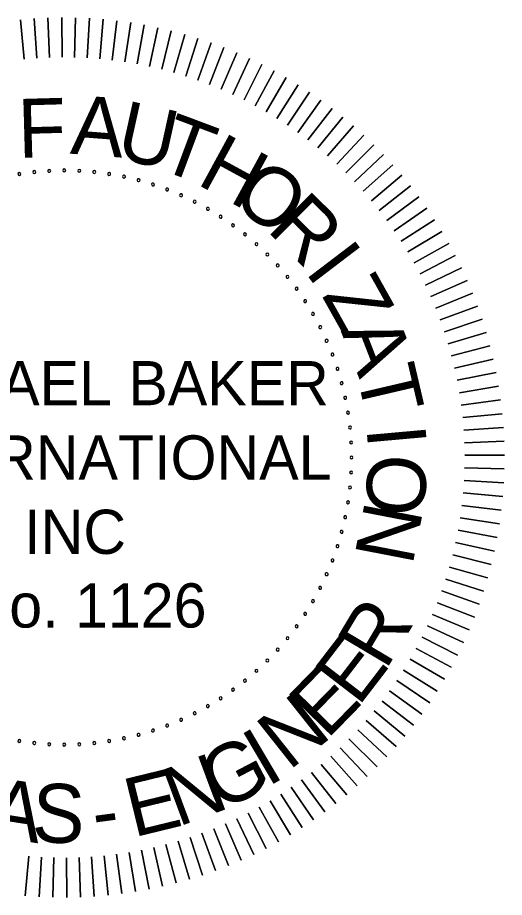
# Model space of a CAD drawing. Extents: x -35254 to 17396, y -8913 to 11592.
# Drawn here: x 6524 to 7900, y -5972 to -3484 of the extents above; entities that cross this region are included whole.
import ezdxf

# ---------------------------------------------------------------- set-up
doc = ezdxf.new("R2010")
doc.units = 0
doc.layers.add('G-ANNO-TEXT', color=7, linetype='Continuous')

msp = doc.modelspace()

# ---------------------------------------------------------------- linework, layer by layer
at = {"layer": 'G-ANNO-TEXT'}
for points in [[(6649.7, -3595.9), (6649.1, -3483.7)], [(6649.1, -3483.7), (6649.7, -3595.9)], [(6685.3, -3596.3), (6688.2, -3484.1)], [(6688.2, -3484.1), (6685.3, -3596.3)], [(6543.2, -3601.5), (6532, -3489.9)], [(6532, -3489.9), (6543.2, -3601.5)], [(6578.7, -3598.6), (6571, -3486.6)], [(6571, -3486.6), (6578.7, -3598.6)], [(6614.2, -3596.7), (6610, -3484.5)], [(6610, -3484.5), (6614.2, -3596.7)], [(6720.8, -3597.8), (6727.3, -3485.7)], [(6727.3, -3485.7), (6720.8, -3597.8)], [(6756.3, -3600.4), (6766.3, -3488.6)], [(6766.3, -3488.6), (6756.3, -3600.4)], [(6791.7, -3604.1), (6805.1, -3492.6)], [(6805.1, -3492.6), (6791.7, -3604.1)], [(6826.9, -3608.9), (6843.9, -3497.9)], [(6843.9, -3497.9), (6826.9, -3608.9)], [(6862, -3614.8), (6882.4, -3504.4)], [(6882.4, -3504.4), (6862, -3614.8)], [(6896.9, -3621.8), (6920.7, -3512.2)], [(6920.7, -3512.2), (6896.9, -3621.8)], [(6931.5, -3629.9), (6958.8, -3521.1)], [(6958.8, -3521.1), (6931.5, -3629.9)], [(6965.9, -3639.1), (6996.6, -3531.2)], [(6996.6, -3531.2), (6965.9, -3639.1)], [(6999.9, -3649.4), (7034, -3542.5)], [(7034, -3542.5), (6999.9, -3649.4)], [(7033.6, -3660.7), (7071, -3554.9)], [(7071, -3554.9), (7033.6, -3660.7)], [(7067, -3673.1), (7107.7, -3568.5)], [(7107.7, -3568.5), (7067, -3673.1)], [(7099.9, -3686.5), (7143.9, -3583.3)], [(7143.9, -3583.3), (7099.9, -3686.5)], [(7132.4, -3701), (7179.6, -3599.2)], [(7179.6, -3599.2), (7132.4, -3701)], [(7164.4, -3716.5), (7214.8, -3616.2)], [(7214.8, -3616.2), (7164.4, -3716.5)], [(7195.9, -3732.9), (7249.5, -3634.3)], [(7249.5, -3634.3), (7195.9, -3732.9)], [(7226.9, -3750.4), (7283.5, -3653.5)], [(7283.5, -3653.5), (7226.9, -3750.4)], [(7257.4, -3768.8), (7317, -3673.7)], [(7317, -3673.7), (7257.4, -3768.8)], [(7287.2, -3788.2), (7349.8, -3695)], [(7349.8, -3695), (7287.2, -3788.2)], [(7316.4, -3808.4), (7381.9, -3717.3)], [(7381.9, -3717.3), (7316.4, -3808.4)], [(7345, -3829.6), (7413.3, -3740.6)], [(7413.3, -3740.6), (7345, -3829.6)], [(7372.9, -3851.7), (7443.9, -3764.9)], [(7443.9, -3764.9), (7372.9, -3851.7)], [(7400, -3874.7), (7473.8, -3790.1)], [(7473.8, -3790.1), (7400, -3874.7)], [(7502.8, -3816.2), (7426.5, -3898.5)], [(7426.5, -3898.5), (7502.8, -3816.2)], [(7531.1, -3843.3), (7452.2, -3923.1)], [(7452.2, -3923.1), (7531.1, -3843.3)], [(7558.4, -3871.2), (7477, -3948.5)], [(7477, -3948.5), (7558.4, -3871.2)], [(7584.9, -3900), (7501.1, -3974.6)], [(7501.1, -3974.6), (7584.9, -3900)], [(7610.4, -3929.5), (7524.4, -4001.6)], [(7524.4, -4001.6), (7610.4, -3929.5)], [(7635.1, -3959.9), (7546.8, -4029.2)], [(7546.8, -4029.2), (7635.1, -3959.9)], [(7658.7, -3991), (7568.3, -4057.5)], [(7568.3, -4057.5), (7658.7, -3991)], [(7681.4, -4022.9), (7588.9, -4086.5)], [(7588.9, -4086.5), (7681.4, -4022.9)], [(7703, -4055.5), (7608.6, -4116.1)], [(7608.6, -4116.1), (7703, -4055.5)], [(7723.6, -4088.7), (7627.3, -4146.3)], [(7627.3, -4146.3), (7723.6, -4088.7)], [(7743.2, -4122.5), (7645.1, -4177.1)], [(7645.1, -4177.1), (7743.2, -4122.5)], [(7761.7, -4157), (7662, -4208.5)], [(7662, -4208.5), (7761.7, -4157)], [(7779.1, -4192), (7677.8, -4240.3)], [(7677.8, -4240.3), (7779.1, -4192)], [(7795.3, -4227.5), (7692.6, -4272.7)], [(7692.6, -4272.7), (7795.3, -4227.5)], [(7810.5, -4263.6), (7706.4, -4305.4)], [(7706.4, -4305.4), (7810.5, -4263.6)], [(7824.5, -4300), (7719.1, -4338.6)], [(7719.1, -4338.6), (7824.5, -4300)], [(7837.4, -4337), (7730.9, -4372.2)], [(7730.9, -4372.2), (7837.4, -4337)], [(7849.1, -4374.3), (7741.5, -4406.2)], [(7741.5, -4406.2), (7849.1, -4374.3)], [(7859.6, -4411.9), (7751.1, -4440.4)], [(7751.1, -4440.4), (7859.6, -4411.9)], [(7869, -4449.9), (7759.6, -4475)], [(7759.6, -4475), (7869, -4449.9)], [(7877.1, -4488.1), (7767, -4509.7)], [(7767, -4509.7), (7877.1, -4488.1)], [(7884, -4526.6), (7773.3, -4544.8)], [(7773.3, -4544.8), (7884, -4526.6)], [(7889.8, -4565.3), (7778.5, -4579.9)], [(7778.5, -4579.9), (7889.8, -4565.3)], [(7894.3, -4604.1), (7782.6, -4615.3)], [(7782.6, -4615.3), (7894.3, -4604.1)], [(7897.5, -4643), (7785.6, -4650.7)], [(7785.6, -4650.7), (7897.5, -4643)], [(7899.6, -4682.1), (7787.5, -4686.2)], [(7787.5, -4686.2), (7899.6, -4682.1)], [(7900.4, -4721.2), (7788.2, -4721.8)], [(7788.2, -4721.8), (7900.4, -4721.2)], [(7900, -4760.3), (7787.9, -4757.4)], [(7787.9, -4757.4), (7900, -4760.3)], [(7898.4, -4799.3), (7786.4, -4792.9)], [(7786.4, -4792.9), (7898.4, -4799.3)], [(7895.6, -4838.3), (7783.8, -4828.4)], [(7783.8, -4828.4), (7895.6, -4838.3)], [(7891.5, -4877.2), (7780.1, -4863.7)], [(7780.1, -4863.7), (7891.5, -4877.2)], [(7886.2, -4915.9), (7775.3, -4899)], [(7775.3, -4899), (7886.2, -4915.9)], [(7879.7, -4954.5), (7769.3, -4934)], [(7769.3, -4934), (7879.7, -4954.5)], [(7872, -4992.8), (7762.3, -4968.9)], [(7762.3, -4968.9), (7872, -4992.8)], [(7863.1, -5030.8), (7754.2, -5003.5)], [(7754.2, -5003.5), (7863.1, -5030.8)], [(7853, -5068.6), (7745, -5037.9)], [(7745, -5037.9), (7853, -5068.6)], [(7841.7, -5106), (7734.8, -5072)], [(7734.8, -5072), (7841.7, -5106)], [(7829.2, -5143.1), (7723.4, -5105.7)], [(7723.4, -5105.7), (7829.2, -5143.1)], [(7815.6, -5179.7), (7711, -5139)], [(7711, -5139), (7815.6, -5179.7)], [(7800.8, -5215.9), (7697.6, -5171.9)], [(7697.6, -5171.9), (7800.8, -5215.9)], [(7785, -5251.7), (7683.2, -5204.4)], [(7683.2, -5204.4), (7785, -5251.7)], [(7768, -5286.9), (7667.7, -5236.5)], [(7667.7, -5236.5), (7768, -5286.9)], [(7749.9, -5321.5), (7651.2, -5268)], [(7651.2, -5268), (7749.9, -5321.5)], [(7730.7, -5355.6), (7633.8, -5299)], [(7633.8, -5299), (7730.7, -5355.6)], [(7710.4, -5389), (7615.4, -5329.4)], [(7615.4, -5329.4), (7710.4, -5389)], [(7689.2, -5421.8), (7596, -5359.2)], [(7596, -5359.2), (7689.2, -5421.8)], [(7666.9, -5453.9), (7575.7, -5388.5)], [(7575.7, -5388.5), (7666.9, -5453.9)], [(7643.6, -5485.3), (7554.5, -5417)], [(7554.5, -5417), (7643.6, -5485.3)], [(7619.3, -5516), (7532.4, -5444.9)], [(7532.4, -5444.9), (7619.3, -5516)], [(7594.1, -5545.8), (7509.5, -5472.1)], [(7509.5, -5472.1), (7594.1, -5545.8)], [(7567.9, -5574.9), (7485.7, -5498.5)], [(7485.7, -5498.5), (7567.9, -5574.9)], [(7540.9, -5603.1), (7461.1, -5524.2)], [(7461.1, -5524.2), (7540.9, -5603.1)], [(7512.9, -5630.5), (7435.7, -5549.1)], [(7435.7, -5549.1), (7512.9, -5630.5)], [(7484.2, -5656.9), (7409.5, -5573.2)], [(7409.5, -5573.2), (7484.2, -5656.9)], [(7454.6, -5682.5), (7382.6, -5596.4)], [(7382.6, -5596.4), (7454.6, -5682.5)], [(7424.2, -5707.1), (7354.9, -5618.8)], [(7354.9, -5618.8), (7424.2, -5707.1)], [(7393.1, -5730.8), (7326.6, -5640.3)], [(7326.6, -5640.3), (7393.1, -5730.8)], [(7361.2, -5753.4), (7297.6, -5660.9)], [(7297.6, -5660.9), (7361.2, -5753.4)], [(7328.7, -5775.1), (7268, -5680.6)], [(7268, -5680.6), (7328.7, -5775.1)], [(7261.6, -5815.2), (7207, -5717.2)], [(7207, -5717.2), (7261.6, -5815.2)], [(7295.5, -5795.7), (7237.8, -5699.4)], [(7237.8, -5699.4), (7295.5, -5795.7)], [(7227.2, -5833.7), (7175.7, -5734)], [(7175.7, -5734), (7227.2, -5833.7)], [(7156.6, -5867.4), (7111.5, -5764.6)], [(7111.5, -5764.6), (7156.6, -5867.4)], [(7192.2, -5851.1), (7143.8, -5749.8)], [(7143.8, -5749.8), (7192.2, -5851.1)], [(7084.1, -5896.6), (7045.5, -5791.2)], [(7045.5, -5791.2), (7084.1, -5896.6)], [(7120.6, -5882.5), (7078.7, -5778.4)], [(7078.7, -5778.4), (7120.6, -5882.5)], [(6972.2, -5931.7), (6943.7, -5823.1)], [(6943.7, -5823.1), (6972.2, -5931.7)], [(7009.9, -5921.1), (6978, -5813.5)], [(6978, -5813.5), (7009.9, -5921.1)], [(7047.2, -5909.4), (7011.9, -5802.9)], [(7011.9, -5802.9), (7047.2, -5909.4)], [(6857.6, -5956.1), (6839.4, -5845.3)], [(6839.4, -5845.3), (6857.6, -5956.1)], [(6896, -5949.1), (6874.4, -5839)], [(6874.4, -5839), (6896, -5949.1)], [(6934.3, -5941), (6909.2, -5831.6)], [(6909.2, -5831.6), (6934.3, -5941)], [(6545.8, -5967.6), (6555.8, -5855.8)], [(6555.8, -5855.8), (6545.8, -5967.6)], [(6584.8, -5970.5), (6591.3, -5858.4)], [(6591.3, -5858.4), (6584.8, -5970.5)], [(6623.9, -5972.1), (6626.8, -5859.9)], [(6626.8, -5859.9), (6623.9, -5972.1)], [(6663, -5972.5), (6662.4, -5860.3)], [(6662.4, -5860.3), (6663, -5972.5)], [(6702.1, -5971.7), (6697.9, -5859.5)], [(6697.9, -5859.5), (6702.1, -5971.7)], [(6741.1, -5969.6), (6733.4, -5857.6)], [(6733.4, -5857.6), (6741.1, -5969.6)], [(6780.1, -5966.3), (6768.9, -5854.6)], [(6768.9, -5854.6), (6780.1, -5966.3)], [(6818.9, -5961.8), (6804.2, -5850.5)], [(6804.2, -5850.5), (6818.9, -5961.8)]]:
    msp.add_lwpolyline(points, dxfattribs=at)
for centre, start, end in [((6529, -3925.9), 9, 189), ((6529, -3925.9), 189, 9), ((6571.2, -3920.4), 6, 186), ((6571.2, -3920.4), 186, 6), ((6613.5, -3917.1), 3, 183), ((6613.5, -3917.1), 183, 3), ((6656, -3915.9), 0, 180), ((6656, -3915.9), 180, 0), ((6698.6, -3917.1), 357, 177), ((6698.6, -3917.1), 177, 357), ((6740.9, -3920.4), 354, 174), ((6740.9, -3920.4), 174, 354), ((6783.1, -3925.9), 171, 351), ((6783.1, -3925.9), 351, 171), ((6824.9, -3933.7), 348, 168), ((6824.9, -3933.7), 168, 348), ((6866.2, -3943.6), 165, 345), ((6866.2, -3943.6), 345, 165), ((6907, -3955.7), 162, 342), ((6907, -3955.7), 342, 162), ((6947.1, -3969.9), 159, 339), ((6947.1, -3969.9), 339, 159), ((6986.4, -3986.2), 336, 156), ((6986.4, -3986.2), 156, 336), ((7024.8, -4004.5), 153, 333), ((7024.8, -4004.5), 333, 153), ((7062.1, -4024.8), 150, 330), ((7062.1, -4024.8), 330, 150), ((7098.4, -4047), 147, 327), ((7098.4, -4047), 327, 147), ((7133.4, -4071.1), 144, 324), ((7133.4, -4071.1), 324, 144), ((7167.1, -4096.9), 141, 321), ((7167.1, -4096.9), 321, 141), ((7199.5, -4124.6), 138, 318), ((7199.5, -4124.6), 318, 138), ((7230.3, -4153.8), 135, 315), ((7230.3, -4153.8), 315, 135), ((7259.6, -4184.7), 312, 132), ((7259.6, -4184.7), 132, 312), ((7287.2, -4217), 129, 309), ((7287.2, -4217), 309, 129), ((7313.1, -4250.7), 126, 306), ((7313.1, -4250.7), 306, 126), ((7337.2, -4285.8), 123, 303), ((7337.2, -4285.8), 303, 123), ((7359.4, -4322), 120, 300), ((7359.4, -4322), 300, 120), ((7379.7, -4359.4), 297, 117), ((7379.7, -4359.4), 117, 297), ((7398, -4397.8), 114, 294), ((7398, -4397.8), 294, 114), ((7414.3, -4437), 111, 291), ((7414.3, -4437), 291, 111), ((7428.4, -4477.1), 108, 288), ((7428.4, -4477.1), 288, 108), ((7440.5, -4517.9), 105, 285), ((7440.5, -4517.9), 285, 105), ((7450.4, -4559.2), 102, 282), ((7450.4, -4559.2), 282, 102), ((7458.2, -4601), 99, 279), ((7458.2, -4601), 279, 99), ((7463.7, -4643.2), 96, 276), ((7463.7, -4643.2), 276, 96), ((7467.1, -4685.6), 93, 273), ((7467.1, -4685.6), 273, 93), ((7468.2, -4728.1), 90, 270), ((7468.2, -4728.1), 270, 90), ((7467.1, -4770.6), 87, 267), ((7467.1, -4770.6), 267, 87), ((7463.7, -4813), 84, 264), ((7463.7, -4813), 264, 84), ((7458.2, -4855.1), 81, 261), ((7458.2, -4855.1), 261, 81), ((7450.4, -4896.9), 78, 258), ((7450.4, -4896.9), 258, 78), ((7440.5, -4938.3), 75, 255), ((7440.5, -4938.3), 255, 75), ((7428.4, -4979.1), 72, 252), ((7428.4, -4979.1), 252, 72), ((7414.3, -5019.1), 69, 249), ((7414.3, -5019.1), 249, 69), ((7398, -5058.4), 66, 246), ((7398, -5058.4), 246, 66), ((7379.7, -5096.8), 63, 243), ((7379.7, -5096.8), 243, 63), ((7359.4, -5134.2), 60, 240), ((7359.4, -5134.2), 240, 60), ((7337.2, -5170.4), 57, 237), ((7337.2, -5170.4), 237, 57), ((7313.1, -5205.5), 54, 234), ((7313.1, -5205.5), 234, 54), ((7287.2, -5239.2), 51, 231), ((7287.2, -5239.2), 231, 51), ((7259.6, -5271.5), 48, 228), ((7259.6, -5271.5), 228, 48), ((7230.3, -5302.4), 45, 225), ((7230.3, -5302.4), 225, 45), ((7199.5, -5331.6), 42, 222), ((7199.5, -5331.6), 222, 42), ((7167.1, -5359.3), 39, 219), ((7167.1, -5359.3), 219, 39), ((7133.4, -5385.1), 36, 216), ((7133.4, -5385.1), 216, 36), ((7098.4, -5409.2), 33, 213), ((7098.4, -5409.2), 213, 33), ((7024.8, -5451.7), 27, 207), ((7024.8, -5451.7), 207, 27), ((7062.1, -5431.4), 30, 210), ((7062.1, -5431.4), 210, 30), ((6986.4, -5470), 24, 204), ((6986.4, -5470), 204, 24), ((6907, -5500.5), 18, 198), ((6907, -5500.5), 198, 18), ((6947.1, -5486.3), 21, 201), ((6947.1, -5486.3), 201, 21), ((6824.9, -5522.5), 12, 192), ((6824.9, -5522.5), 192, 12), ((6866.2, -5512.6), 15, 195), ((6866.2, -5512.6), 195, 15), ((6529, -5530.2), 171, 351), ((6529, -5530.2), 351, 171), ((6571.2, -5535.8), 354, 174), ((6571.2, -5535.8), 174, 354), ((6613.5, -5539.1), 357, 177), ((6613.5, -5539.1), 177, 357), ((6656, -5540.2), 0, 180), ((6656, -5540.2), 180, 0), ((6698.6, -5539.1), 3, 183), ((6698.6, -5539.1), 183, 3), ((6740.9, -5535.8), 6, 186), ((6740.9, -5535.8), 186, 6), ((6783.1, -5530.2), 9, 189), ((6783.1, -5530.2), 189, 9)]:
    msp.add_arc(centre, 4.17, start, end, dxfattribs=at)

# ---------------------------------------------------------------- texts
for s, rotation, p in [('A', 355.5955, (6671.2, -3868.5)), ('F', 1.5867, (6526.7, -3880.8)), ('U', 347.5481, (6797.3, -3880.4)), ('T', 339.5007, (6913.7, -3908.2)), ('H', 331.4533, (7026.7, -3952.8)), ('O', 323.4059, (7122.4, -4005.5)), ('R', 315.3585, (7225.7, -4084.5)), ('I', 307.3112, (7334.1, -4201.9)), ('Z', 299.2638, (7383, -4269.8)), ('A', 291.2164, (7437.6, -4370.1)), ('T', 283.169, (7481.2, -4488)), ('I', 275.1216, (7510.1, -4644)), ('O', 267.0743, (7516, -4715.6)), ('N', 259.0269, (7507.2, -4846.7)), ('R', 59.2262, (7564.7, -5332.5)), ('E', 52.4765, (7487.4, -5435.1)), ('E', 45.7268, (7398.5, -5527.9)), ('N', 38.4196, (7290.8, -5615.9)), ('I', 30.5495, (7230.2, -5661.8)), ('G', 27.7404, (7098.5, -5731.7)), ('N', 20.4332, (6977.1, -5773.8)), ('E', 13.6835, (6851.5, -5803.2)), ('A', 351.1991, (6435.5, -5796.9)), ('S', 357.9489, (6562.7, -5815.4)), ('-', 7.5077, (6744.5, -5815.8))]:
    msp.add_text(s, height=166.7, rotation=rotation, dxfattribs=at).set_placement(p)
for s, height, p in [('MICHAEL BAKER', 125.016, (6047.8, -4580.3)), (' INTERNATIONAL', 125.016, (6027.7, -4790.5)), ('INC', 125.02, (6542.8, -5000.8)), (' No. 1126', 125.02, (6333.4, -5209.1))]:
    msp.add_text(s, height=height, dxfattribs=at).set_placement(p)

doc.saveas('drawing.dxf')
